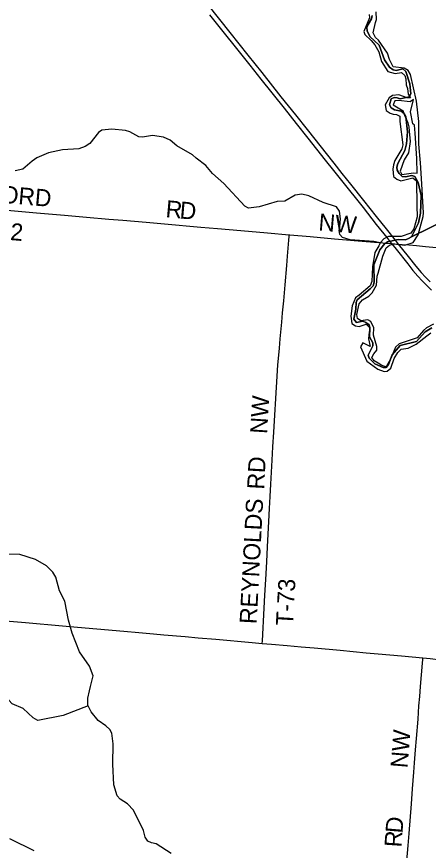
# Model space of a CAD drawing. Extents: x -51392 to 1635000, y 156707 to 696232.
# Drawn here: x 108334 to 115578, y 488186 to 502833 of the extents above; entities that cross this region are included whole.
import ezdxf

# ---------------------------------------------------------------- set-up
doc = ezdxf.new("R2010")
doc.units = 0
for name, color, linetype in [('GM_X_County_Road', 7, 'Continuous'), ('GM_X_County_Road_Text', 7, 'Continuous'), ('GM_X_Major_River', 7, 'Continuous'), ('GM_X_Minor_River', 7, 'Continuous'), ('GM_X_Township', 7, 'Continuous'), ('GM_X_Township_Road', 7, 'Continuous'), ('GM_X_Township_Road_Text', 7, 'Continuous'), ('GM_X_US_Route', 7, 'Continuous')]:
    doc.layers.add(name, color=color, linetype=linetype)

msp = doc.modelspace()

# ---------------------------------------------------------------- linework, layer by layer
at = {"layer": 'GM_X_County_Road'}
for points in [[(107240, 499518), (107573, 499486), (108683, 499389), (109173, 499346), (109565, 499313), (109957, 499278), (110202, 499256), (110611, 499220), (110937, 499191), (111574, 499136), (111868, 499110), (112276, 499075), (112750, 499034), (113131, 499001)], [(113131, 499001), (113142, 499000), (113501, 498969), (113926, 498932), (114481, 498885), (114775, 498859), (114828, 498854)], [(114828, 498854), (114931, 498846), (115045, 498838), (115119, 498832), (115233, 498822), (115369, 498810), (115526, 498796), (115722, 498779)], [(106704, 492369), (106725, 492362), (106773, 492351), (106837, 492340), (106935, 492329), (107180, 492305), (107409, 492284), (107588, 492268), (107932, 492238), (108209, 492213), (108487, 492189), (109141, 492132), (109402, 492109), (109746, 492078), (110219, 492036), (110481, 492013), (110742, 491989), (110922, 491974), (111298, 491941), (111527, 491921), (111837, 491893), (112475, 491837), (112654, 491822)], [(112654, 491822), (112818, 491807), (113096, 491783), (113341, 491761), (113570, 491742), (114027, 491700), (114485, 491658), (114697, 491640), (115106, 491605), (115482, 491570)], [(115184, 487794), (115221, 488268), (115239, 488481), (115279, 489004), (115300, 489266), (115322, 489561), (115334, 489724), (115354, 489953), (115371, 490149), (115396, 490493), (115413, 490722), (115427, 490886), (115440, 491066), (115475, 491474), (115480, 491540), (115482, 491570)], [(115482, 491570), (115612, 491555), (115791, 491530), (115986, 491502), (116181, 491475), (116473, 491435), (116928, 491373), (117189, 491339), (117449, 491304), (117644, 491276), (117741, 491263), (117871, 491245), (118034, 491224), (118196, 491201), (118553, 491149), (118748, 491122), (118750, 491122)], [(108205, 488391), (108383, 488306), (108472, 488264), (108575, 488214), (108633, 488183)]]:
    msp.add_lwpolyline(points, dxfattribs=at)
at = {"layer": 'GM_X_Major_River'}
for points in [[(115315, 501378), (115259, 501337), (115050, 501362), (114988, 501355), (114956, 501285), (115132, 501177), (115140, 501143), (115159, 501104), (115214, 500966), (115234, 500900), (115241, 500822)], [(115241, 500822), (115258, 500639), (115229, 500441), (115150, 500319), (115080, 500119), (115112, 500059), (115232, 500080), (115317, 500089), (115379, 500083), (115373, 500341), (115347, 500786), (115333, 500927), (115307, 500953), (115264, 501164), (115315, 501378)]]:
    msp.add_lwpolyline(points, dxfattribs=at)
at = {"layer": 'GM_X_Minor_River'}
for points in [[(114535, 502872), (114540, 502815), (114440, 502570), (114458, 502519), (114572, 502416), (114635, 502336), (114709, 502217), (114752, 502048), (114863, 501869), (114995, 501836), (115106, 501853), (115162, 501799), (115181, 501742), (115187, 501638), (115208, 501574), (115222, 501469), (115261, 501407), (115207, 501407), (115057, 501458), (114949, 501449), (114888, 501410), (114815, 501286), (114838, 501185), (114908, 501135), (114960, 501120), (115019, 501114), (115077, 501085), (115076, 500993), (115131, 500584), (115109, 500510), (114987, 500304), (114963, 500232), (114954, 500154), (114963, 500026), (115021, 499979), (115095, 499951), (115304, 499999), (115368, 499951), (115373, 499509), (115382, 499315), (115322, 499107), (115268, 499029), (115097, 498970), (114876, 498968), (114797, 498932), (114735, 498866), (114706, 498809), (114635, 498687), (114597, 498440), (114583, 498182), (114555, 498104), (114361, 497941), (114297, 497891), (114237, 497751), (114212, 497573), (114231, 497440), (114297, 497402), (114363, 497387), (114486, 497433), (114550, 497364), (114533, 497246), (114525, 497170), (114552, 497041), (114422, 497100), (114381, 497032)], [(115670, 497432), (115545, 497367), (115495, 497321), (115380, 497193), (115062, 497083), (114999, 497024), (114920, 496830), (114834, 496680), (114760, 496703), (114696, 496745), (114626, 496784), (114583, 496844), (114617, 496912), (114672, 496972), (114672, 497040), (114615, 497239), (114618, 497369), (114567, 497476), (114515, 497505), (114388, 497489), (114332, 497532), (114321, 497600), (114358, 497786), (114417, 497860), (114528, 497920), (114590, 497981), (114665, 498117), (114680, 498271), (114693, 498327), (114775, 498624), (114836, 498771), (114893, 498821), (114963, 498843), (115164, 498821), (115311, 498864), (115400, 498998), (115488, 499320), (115493, 499388), (115459, 499990), (115442, 500263), (115412, 500596), (115409, 500937), (115413, 500993), (115369, 501350), (115266, 501816), (115223, 501888), (115155, 501929), (114956, 501952), (114893, 502079), (114857, 502192), (114702, 502423), (114650, 502470), (114605, 502550), (114646, 502728), (114663, 502786), (114657, 502917)], [(115315, 501378), (115259, 501337), (115050, 501362), (114988, 501355), (114956, 501285), (115132, 501177), (115140, 501143), (115159, 501104), (115214, 500966), (115234, 500900), (115241, 500822)], [(115241, 500822), (115258, 500639), (115229, 500441), (115150, 500319), (115080, 500119), (115112, 500059), (115232, 500080), (115317, 500089), (115379, 500083), (115373, 500341), (115347, 500786), (115333, 500927), (115307, 500953), (115264, 501164), (115315, 501378)], [(114732, 498862), (114616, 498883), (114201, 498910), (114069, 498952), (114021, 499004), (114009, 499076), (114022, 499148), (114031, 499283), (114016, 499415), (113962, 499490), (113724, 499570), (113474, 499684), (113349, 499713), (113237, 499697), (113052, 499591), (112919, 499586), (112601, 499490), (112416, 499471), (112350, 499505), (111982, 499905), (111782, 500079), (111665, 500216), (111495, 500350), (111427, 500406), (111151, 500563), (111036, 500662), (110916, 500715), (110723, 500748), (110546, 500716), (110486, 500724), (110328, 500811), (110246, 500834), (110011, 500854), (109835, 500837), (109776, 500799), (109620, 500602), (109540, 500551), (109425, 500509), (109138, 500491), (108893, 500443), (108689, 500354), (108609, 500295), (108443, 500152), (108306, 500127)], [(114381, 497032), (114498, 496783), (114690, 496637), (114800, 496600), (114854, 496604), (114916, 496655), (114978, 496829), (115039, 496935), (115097, 496993), (115220, 497010), (115365, 497079), (115551, 497226), (115621, 497276)], [(109440, 491673), (109310, 491999), (109245, 492230), (109183, 492561), (109090, 492744), (109021, 492987), (108968, 493072), (108860, 493183), (108666, 493295), (108390, 493381), (108089, 493391)], [(111052, 488131), (110786, 488301), (110704, 488316), (110640, 488344), (110594, 488419), (110567, 488533), (110388, 488889), (110285, 489004), (110155, 489087), (110103, 489142), (110046, 489335), (110025, 489698), (110033, 490057), (110006, 490247), (109973, 490310), (109905, 490374), (109765, 490468), (109643, 490619), (109588, 490737), (109585, 490862), (109614, 490990), (109632, 491064), (109680, 491254), (109613, 491421), (109440, 491673)], [(109592, 490724), (109153, 490556), (108707, 490469), (108623, 490516), (108450, 490676), (108255, 490761), (108196, 490824), (108127, 491013), (107989, 491088), (107857, 491127), (107777, 491168), (107671, 491281)]]:
    msp.add_lwpolyline(points, dxfattribs=at)
at = {"layer": 'GM_X_Township'}
for points in [[(114587, 502854), (114577, 502798), (114518, 502697), (114498, 502641), (114503, 502585), (114548, 502483), (114714, 502332), (114807, 502074), (114894, 501944), (114959, 501897), (115013, 501885), (115130, 501914), (115180, 501871), (115251, 501653), (115270, 501478), (115243, 501424), (115082, 501391), (115028, 501408), (114974, 501414), (114924, 501387), (114892, 501283), (114925, 501229), (114984, 501195), (115100, 501172), (115153, 501134), (115181, 501079), (115208, 500812), (115196, 500601), (115165, 500479), (115038, 500255), (115021, 500187), (115027, 500135), (115062, 500075), (115117, 500023), (115175, 500020), (115287, 500041), (115340, 500023), (115401, 499919), (115453, 499689), (115440, 499378), (115403, 499209), (115281, 498964), (115229, 498938), (115173, 498911), (115044, 498919), (114860, 498876), (114833, 498860), (114810, 498845), (114725, 498736), (114620, 498475), (114625, 498166), (114604, 498105), (114556, 498049), (114325, 497860), (114305, 497810), (114304, 497696), (114267, 497519), (114312, 497459), (114422, 497482), (114479, 497462), (114536, 497417), (114546, 497365), (114545, 497208), (114603, 497100), (114603, 497050), (114516, 496887), (114535, 496833), (114634, 496734), (114781, 496667), (114838, 496667), (114879, 496720), (114940, 496893), (115081, 497055), (115370, 497127), (115519, 497295), (115637, 497368)], [(118218, 500406), (115281, 498964), (115403, 499209), (115440, 499378), (115453, 499689), (115401, 499919), (115340, 500023), (115287, 500041), (115175, 500020), (115117, 500023), (115062, 500075), (115027, 500135), (115021, 500187), (115038, 500255), (115165, 500479), (115196, 500601), (115208, 500812), (115181, 501079), (115153, 501134), (115100, 501172), (114984, 501195), (114925, 501229), (114892, 501283), (114924, 501387), (114974, 501414), (115028, 501408), (115082, 501391), (115243, 501424), (115270, 501478), (115251, 501653), (115180, 501871), (115130, 501914), (115013, 501885), (114959, 501897), (114894, 501944), (114807, 502074), (114714, 502332), (114548, 502483), (114503, 502585), (114498, 502641), (114518, 502697), (114577, 502798), (114587, 502854)], [(115637, 497368), (115519, 497295), (115370, 497127), (115081, 497055), (114940, 496893), (114879, 496720), (114838, 496667), (114781, 496667), (114634, 496734), (114535, 496833), (114516, 496887), (114603, 497050), (114603, 497100), (114545, 497208), (114546, 497365), (114536, 497417), (114479, 497462), (114422, 497482), (114312, 497459), (114267, 497519), (114304, 497696), (114305, 497810), (114325, 497860), (114556, 498049), (114604, 498105), (114625, 498166), (114620, 498475), (114725, 498736), (114810, 498845), (114833, 498860), (114860, 498876), (115044, 498919), (115173, 498911), (115229, 498938), (115281, 498964), (118218, 500406)]]:
    msp.add_lwpolyline(points, dxfattribs=at)
at = {"layer": 'GM_X_Township_Road'}
msp.add_lwpolyline([(112654, 491822), (112657, 491865), (112687, 492438), (112701, 492668), (112716, 492946), (112734, 493257), (112748, 493520), (112771, 493962), (112783, 494191), (112796, 494404), (112808, 494617), (112831, 495043), (112843, 495273), (112858, 495535), (112875, 495830), (112893, 496124), (112919, 496517), (112932, 496714), (112941, 496828), (112959, 497008), (112973, 497171), (112998, 497466), (113013, 497629), (113032, 497842), (113056, 498119), (113085, 498463), (113099, 498626), (113122, 498904), (113128, 498970), (113131, 499001)], dxfattribs=at)
at = {"layer": 'GM_X_US_Route'}
for points in [[(111697, 503044), (112085, 502557), (112401, 502158), (112647, 501851), (112984, 501427), (113240, 501107), (113444, 500850), (113913, 500259), (114057, 500080), (114210, 499888), (114435, 499605), (114660, 499323), (114834, 499105), (114992, 498905), (115045, 498838), (115221, 498617), (115356, 498452), (115452, 498340), (115529, 498255), (115609, 498172)], [(111729, 502866), (112435, 501981), (112629, 501737), (113038, 501224), (113253, 500954), (113457, 500697), (113763, 500312), (113906, 500132), (114049, 499952), (114428, 499479), (114662, 499183), (114846, 498952), (114901, 498884), (114931, 498846), (115010, 498747), (115214, 498490), (115307, 498375), (115393, 498276), (115470, 498191), (115550, 498109), (115633, 498029)]]:
    msp.add_lwpolyline(points, dxfattribs=at)

# ---------------------------------------------------------------- texts
at = {"layer": 'GM_X_County_Road_Text'}
for s, rotation, p in [('FORD', 355.1105, (107800, 499587)), ('R', 355.0505, (110947, 499310)), ('D', 355.3422, (111194, 499288)), ('NW', 355.1968, (113637, 499078)), ('C-12', 355.0334, (107569, 498966)), ('NW', 85.3427, (115210, 489623)), ('D', 85.2636, (115121, 488477)), ('R', 86.1042, (115104, 488232))]:
    msp.add_text(s, height=300, rotation=rotation, dxfattribs=at).set_placement(p)
at = {"layer": 'GM_X_Township_Road_Text'}
for s, rotation, p in [('NW', 86.4519, (112739, 495497)), ('RD', 86.9659, (112687, 494520)), ('REYNOLDS', 86.9382, (112555, 492156)), ('T-73', 86.6535, (113193, 492126))]:
    msp.add_text(s, height=300, rotation=rotation, dxfattribs=at).set_placement(p)

doc.saveas('drawing.dxf')
